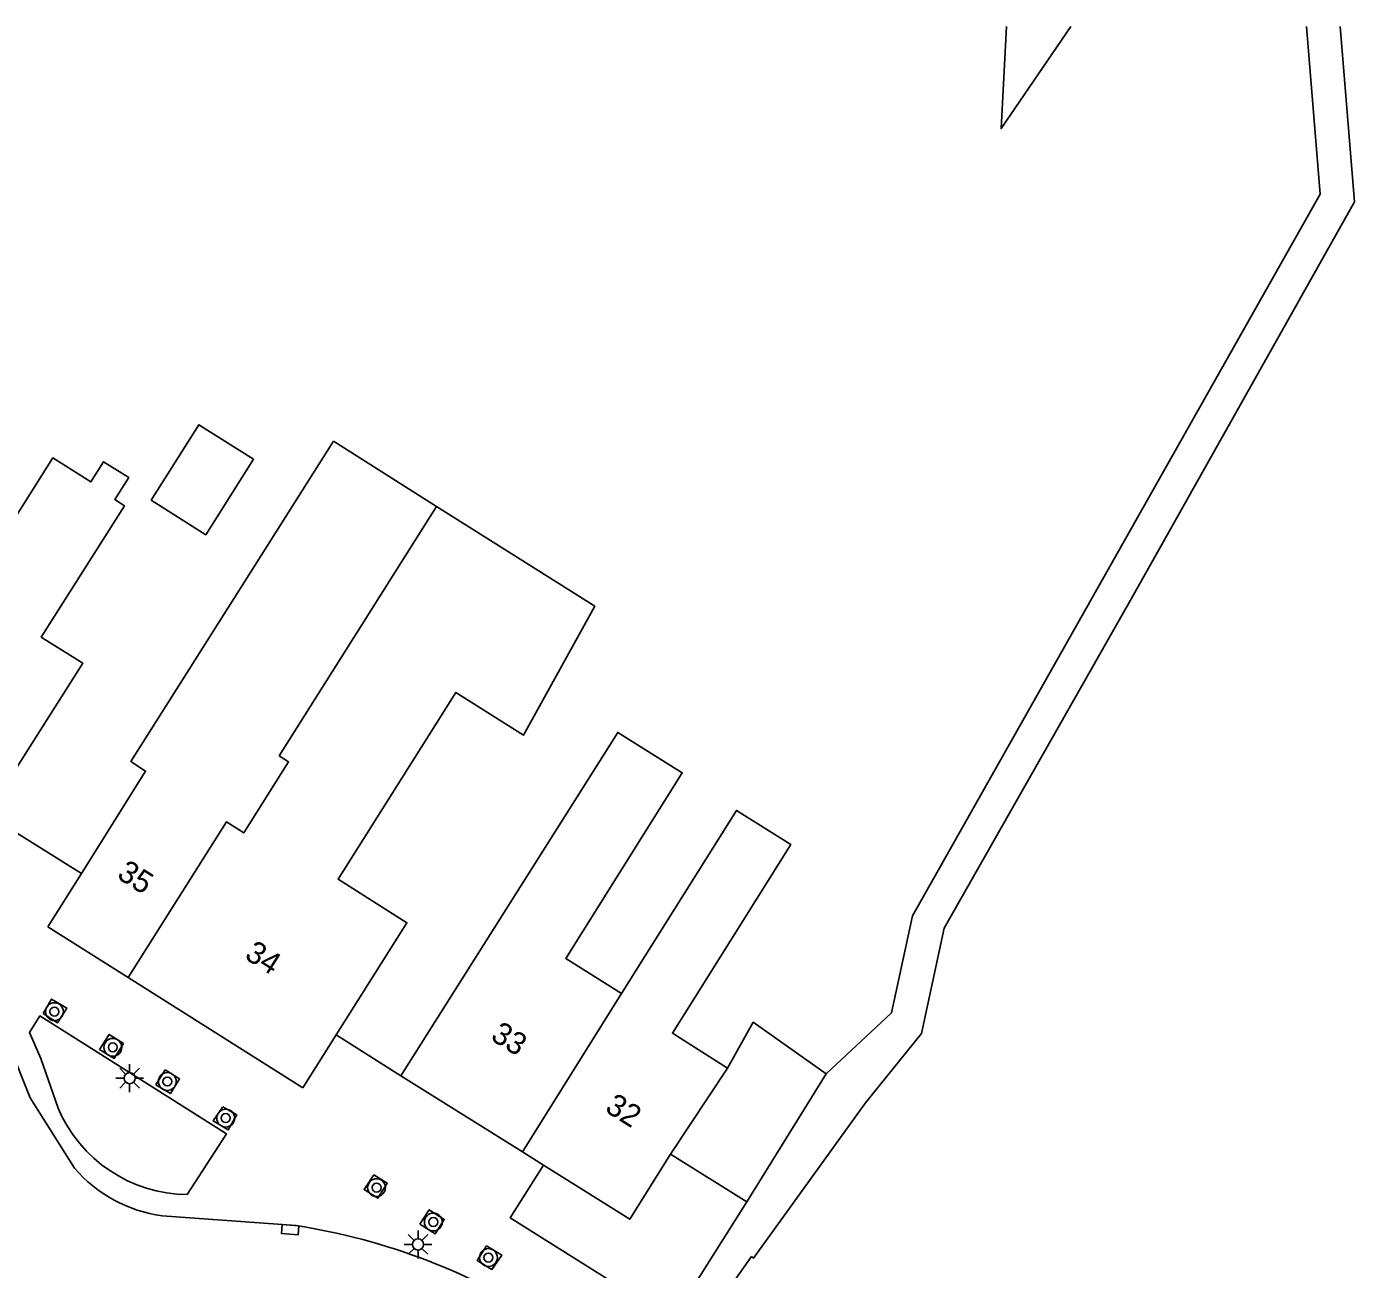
# Model space of a CAD drawing. Extents: x 132573 to 132944, y 398226 to 398676.
# Drawn here: x 132654 to 132713.5, y 398620.6 to 398676.3 of the extents above; entities that cross this region are included whole.
import ezdxf

# ---------------------------------------------------------------- set-up
doc = ezdxf.new("R2010")
doc.units = 0
for name, color, linetype in [('gg-afsc-hekwerk', 7, 'Continuous'), ('gg-anno-huisnummerreeks BGT', 7, 'Continuous'), ('gg-bbg-bijgebouw', 7, 'Continuous'), ('gg-bbg-gedigitaliseerde bebouwing', 7, 'Continuous'), ('gg-bbg-gedigitaliseerde bijgebouw', 7, 'Continuous'), ('gg-bbg-hoofdgebouw', 7, 'Continuous'), ('gg-bbg-tussenscheiding', 7, 'Continuous'), ('gg-knt-verharding', 7, 'Continuous'), ('gt-grn-groengrens', 7, 'Continuous'), ('gt-grn-vlakafsluiter', 7, 'Continuous'), ('gt-symb-boom', 7, 'Continuous'), ('gt-symb-kolk', 7, 'Continuous'), ('gt-symb-lichtmast', 7, 'Continuous')]:
    doc.layers.add(name, color=color, linetype=linetype)

msp = doc.modelspace()

# ---------------------------------------------------------------- linework, layer by layer
at = {"layer": 'gg-afsc-hekwerk'}
for points in [[(132694.479, 398637.847), (132711.977, 398668.823), (132711.359, 398676.345)], [(132700.793, 398676.345), (132697.667, 398671.766), (132697.907, 398676.345)], [(132689.831, 398629.385), (132692.751, 398632.124), (132693.697, 398636.463), (132694.479, 398637.847)]]:
    msp.add_lwpolyline(points, dxfattribs=at)
at = {"layer": 'gg-bbg-bijgebouw'}
msp.add_line((132682.85, 398625.78), (132686.26, 398623.65), dxfattribs=at)
at = {"layer": 'gg-bbg-gedigitaliseerde bebouwing'}
for p, q in [((132672.352, 398654.829), (132667.729, 398657.752)), ((132666.36, 398628.76), (132667.862, 398631.139))]:
    msp.add_line(p, q, dxfattribs=at)
for points in [[(132652.19, 398641.02), (132656.49, 398647.791), (132654.634, 398648.964), (132658.362, 398654.86), (132657.928, 398655.134), (132658.552, 398656.122), (132657.428, 398656.832), (132656.857, 398655.928), (132655.156, 398657.003), (132647.1, 398644.24)], [(132667.862, 398631.139), (132671.028, 398636.157), (132667.938, 398638.107), (132673.225, 398646.484), (132676.254, 398644.572), (132679.45, 398650.349), (132672.352, 398654.829)], [(132680.649, 398632.99), (132678.146, 398634.561), (132683.369, 398642.882), (132680.478, 398644.696), (132670.76, 398629.3)], [(132685.401, 398629.644), (132682.93, 398631.206), (132688.237, 398639.662), (132685.798, 398641.193), (132680.649, 398632.99)]]:
    msp.add_lwpolyline(points, dxfattribs=at)
at = {"layer": 'gg-bbg-gedigitaliseerde bijgebouw'}
msp.add_line((132686.26, 398623.65), (132689.831, 398629.385), dxfattribs=at)
for points in [[(132659.562, 398655.102), (132662.008, 398653.555), (132664.149, 398656.942), (132661.703, 398658.488), (132659.562, 398655.102)], [(132689.831, 398629.385), (132686.554, 398631.696), (132685.401, 398629.644)]]:
    msp.add_lwpolyline(points, dxfattribs=at)
at = {"layer": 'gg-bbg-hoofdgebouw'}
for p, q in [((132654.929, 398635.974), (132656.431, 398638.37)), ((132658.532, 398633.7), (132654.929, 398635.974)), ((132666.36, 398628.76), (132658.532, 398633.7)), ((132676.21, 398625.879), (132670.76, 398629.3)), ((132677.147, 398625.291), (132676.21, 398625.879))]:
    msp.add_line(p, q, dxfattribs=at)
for points in [[(132656.431, 398638.37), (132659.31, 398642.962), (132658.652, 398643.395), (132667.729, 398657.752)], [(132677.147, 398625.291), (132681.02, 398622.86), (132682.85, 398625.78)]]:
    msp.add_lwpolyline(points, dxfattribs=at)
at = {"layer": 'gg-bbg-tussenscheiding'}
for p, q in [((132665.293, 398643.644), (132672.352, 398654.829)), ((132680.649, 398632.99), (132676.21, 398625.879)), ((132685.401, 398629.644), (132682.85, 398625.78))]:
    msp.add_line(p, q, dxfattribs=at)
msp.add_lwpolyline([(132665.293, 398643.644), (132665.724, 398643.372), (132663.714, 398640.187), (132662.936, 398640.678), (132658.532, 398633.7)], dxfattribs=at)
at = {"layer": 'gg-knt-verharding'}
for p, q in [((132656.431, 398638.37), (132652.19, 398641.02)), ((132670.76, 398629.3), (132667.862, 398631.139)), ((132660.056, 398623.011), (132666.062, 398622.58))]:
    msp.add_line(p, q, dxfattribs=at)
for points in [[(132654.716, 398632.087), (132655.359, 398631.668), (132655.774, 398632.332), (132655.098, 398632.732), (132654.716, 398632.087)], [(132655.39, 398627.84), (132654.62, 398630.07), (132654.11, 398631.24), (132654.57, 398631.98), (132662.94, 398626.69), (132661.179, 398623.97)], [(132653.2, 398630.67), (132654.14, 398628.31), (132656.12, 398625.15)], [(132657.245, 398630.468), (132657.672, 398631.143), (132658.317, 398630.74), (132657.908, 398630.074), (132657.245, 398630.468)], [(132659.774, 398628.894), (132660.194, 398629.558), (132660.831, 398629.154), (132660.427, 398628.498), (132659.774, 398628.894)], [(132662.77, 398627.91), (132663.402, 398627.538), (132663.013, 398626.877), (132662.343, 398627.269), (132662.77, 398627.91)], [(132669.54, 398624.857), (132670.145, 398624.481), (132669.722, 398623.81), (132669.11, 398624.191), (132669.54, 398624.857)], [(132677.147, 398625.291), (132675.66, 398622.93), (132682.927, 398618.355)], [(132671.602, 398622.635), (132672.289, 398622.207), (132672.704, 398622.852), (132672.03, 398623.284), (132671.602, 398622.635)], [(132674.598, 398621.67), (132675.278, 398621.254), (132674.839, 398620.614), (132674.181, 398621.019), (132674.598, 398621.67)]]:
    msp.add_lwpolyline(points, dxfattribs=at)
for centre, radius, start, end in [((132661.24, 398630.326), 6.356, 203.02315, 269.45067), ((132660.952, 398629.351), 6.403, 221.00395, 261.95274), ((132661.551, 398593.889), 29.044, 56.97532, 81.06504)]:
    msp.add_arc(centre, radius, start, end, dxfattribs=at)
at = {"layer": 'gt-grn-groengrens'}
msp.add_lwpolyline([(132712.864, 398676.345), (132713.509, 398668.488), (132703.529, 398650.723), (132695.115, 398635.922), (132694.094, 398631.191), (132691.582, 398628.079), (132686.56, 398621.124), (132686.482, 398621.186), (132684.863, 398618.909), (132685.788, 398618.327), (132684.93, 398616.938)], dxfattribs=at)
at = {"layer": 'gt-grn-vlakafsluiter'}
msp.add_line((132682.927, 398618.355), (132686.26, 398623.65), dxfattribs=at)
at = {"layer": 'gt-symb-boom'}
for centre, radius in [((132655.223, 398632.17), 0.4), ((132655.223, 398632.17), 0.2), ((132657.84, 398630.57), 0.4), ((132657.84, 398630.57), 0.2), ((132660.283, 398629.04), 0.4), ((132660.283, 398629.04), 0.2), ((132662.902, 398627.398), 0.4), ((132662.902, 398627.398), 0.2), ((132669.667, 398624.279), 0.4), ((132669.667, 398624.279), 0.2), ((132672.213, 398622.74), 0.4), ((132672.213, 398622.74), 0.2), ((132674.682, 398621.144), 0.4), ((132674.682, 398621.144), 0.2)]:
    msp.add_circle(centre, radius, dxfattribs=at)
at = {"layer": 'gt-symb-kolk'}
msp.add_lwpolyline([(132665.807, 398622.593), (132665.433, 398622.625), (132665.399, 398622.226), (132666.147, 398622.163), (132666.181, 398622.561), (132665.807, 398622.593)], dxfattribs=at)
at = {"layer": 'gt-symb-lichtmast'}
for p, q in [((132658.417, 398629.366), (132658.152, 398629.631)), ((132658.594, 398629.439), (132658.594, 398629.814)), ((132658.771, 398629.366), (132659.036, 398629.631)), ((132658.344, 398629.189), (132657.969, 398629.189)), ((132658.417, 398629.012), (132658.152, 398628.747)), ((132658.594, 398628.939), (132658.594, 398628.564)), ((132659.036, 398628.747), (132658.771, 398629.012)), ((132658.844, 398629.189), (132659.219, 398629.189)), ((132671.525, 398621.982), (132671.525, 398622.357)), ((132671.275, 398621.732), (132670.9, 398621.732)), ((132671.348, 398621.909), (132671.083, 398622.174)), ((132671.702, 398621.909), (132671.967, 398622.174)), ((132671.775, 398621.732), (132672.15, 398621.732)), ((132671.348, 398621.555), (132671.083, 398621.29)), ((132671.525, 398621.482), (132671.525, 398621.107)), ((132671.967, 398621.29), (132671.702, 398621.555))]:
    msp.add_line(p, q, dxfattribs=at)
for centre in [(132658.594, 398629.189), (132671.525, 398621.732)]:
    msp.add_circle(centre, 0.25, dxfattribs=at)

# ---------------------------------------------------------------- texts
at = {"layer": 'gg-anno-huisnummerreeks BGT'}
for s, rotation, p in [('35', 327.7, (132657.977, 398638.189)), ('34', 327.7, (132663.701, 398634.577)), ('33', 327.9, (132674.73, 398630.94)), ('32', 327.9, (132679.858, 398627.722))]:
    msp.add_text(s, height=1, rotation=rotation, dxfattribs=at).set_placement(p)

doc.saveas('drawing.dxf')
